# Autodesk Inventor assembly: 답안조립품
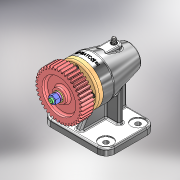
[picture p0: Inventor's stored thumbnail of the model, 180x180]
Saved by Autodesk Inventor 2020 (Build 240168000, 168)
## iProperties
Created: 2024-12
Part Number: 답안조립품
Document SubType Name: Assembly
Designer: 1강의실14
Author: 1강의실14
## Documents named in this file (15)
- C:\Users\1강의실14\Desktop\741204V1019\답안조립품.iam
- C:\Users\1강의실14\Desktop\741204V1019\본체.ipt
- C:\Users\1강의실14\Desktop\741204V1019\축.ipt
- C:\Users\1강의실14\Desktop\741204V1019\앵귤러 볼 베어링 7003A.ipt
- C:\Users\1강의실14\Desktop\741204V1019\앵귤러 볼 제어링 7204A.ipt
- C:\Users\1강의실14\Desktop\741204V1019\평행 키 4x4x14.ipt
- C:\Users\1강의실14\Desktop\741204V1019\그리스 니플 M6x0.75.ipt
- C:\Users\1강의실14\Desktop\741204V1019\실링.ipt
- C:\Users\1강의실14\Desktop\741204V1019\커버.ipt
- C:\Users\1강의실14\Desktop\741204V1019\육각 소켓 머리 볼트 M4x10.ipt
- C:\Users\1강의실14\Desktop\741204V1019\오일 실 20 32 8.ipt
- C:\Users\1강의실14\Desktop\741204V1019\스퍼기어.ipt
- C:\Users\1강의실14\Desktop\741204V1019\육각 너트 M8.ipt
- C:\Users\1강의실14\Desktop\741204V1019\평와셔 M8.ipt
- C:\Users\1강의실14\Desktop\741204V1019\스프링 와셔 M8.ipt
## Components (1 placed, 1 different names)
1. 그리스 니플 M6x0.75:1
